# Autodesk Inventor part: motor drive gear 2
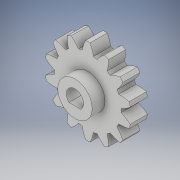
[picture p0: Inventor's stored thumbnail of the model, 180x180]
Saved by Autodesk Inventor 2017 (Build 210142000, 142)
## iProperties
Created: 2016-07
Part Number: motor drive gear 2
Material: Generic
Document SubType Name: Modeling
Designer: Stan
Density: 1 g/cm^3
Appearance: Default
Author: Stan
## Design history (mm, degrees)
sketch "Sketch1"
  geometry: L1 (-2.203, -2.286)-(2.203, -2.286); A1 r 13.958 centre (-11.606, 9.5) between (2.097, 12.157) and (0.818, 15.862); A2 r 13.958 centre (-11.606, 9.5) between (2.097, 12.157) and (0.818, 15.862); A3 r 13.958 centre (-11.606, 9.5) between (2.097, 12.157) and (0.818, 15.862); A4 r 13.958 centre (11.606, 9.5) between (-0.818, 15.862) and (-2.097, 12.157); A5 r 13.958 centre (11.606, 9.5) between (-0.822, 15.854) and (-2.097, 12.157); A6 r 13.958 centre (-11.606, 9.5) between (2.097, 12.157) and (0.822, 15.854); A7 r 13.958 centre (-14.578, 3.524) between (-3.386, 11.863) and (-6.145, 14.646); A8 r 13.958 centre (-14.578, 3.524) between (-3.386, 11.863) and (-6.145, 14.646); A9 r 13.958 centre (-14.578, 3.524) between (-3.386, 11.863) and (-6.145, 14.646); A10 r 13.958 centre (6.334, 13.595) between (-7.619, 13.936) and (-7.164, 10.044); A11 r 13.958 centre (6.334, 13.595) between (-7.62, 13.927) and (-7.164, 10.044); A12 r 13.958 centre (-14.578, 3.524) between (-3.386, 11.863) and (-6.138, 14.64); A13 r 13.958 centre (-14.663, -3.15) between (-8.198, 9.22) and (-11.891, 10.529); A14 r 13.958 centre (-14.663, -3.15) between (-8.198, 9.22) and (-11.891, 10.529); A15 r 13.958 centre (-14.663, -3.15) between (-8.198, 9.22) and (-11.891, 10.529); A16 r 13.958 centre (-0.191, 14.997) between (-12.911, 9.25) and (-10.812, 5.94); A17 r 13.958 centre (-0.191, 14.997) between (-12.908, 9.242) and (-10.812, 5.94); A18 r 13.958 centre (-14.663, -3.15) between (-8.198, 9.22) and (-11.882, 10.528); A19 r 13.958 centre (-11.844, -9.201) between (-11.386, 4.75) and (-15.282, 4.327); A20 r 13.958 centre (-11.844, -9.201) between (-11.386, 4.75) and (-15.282, 4.327); A21 r 13.958 centre (-11.844, -9.201) between (-11.386, 4.75) and (-15.282, 4.327); A22 r 13.958 centre (-6.679, 13.428) between (-15.646, 2.732) and (-12.319, 0.661); A23 r 13.958 centre (-6.679, 13.428) between (-15.639, 2.726) and (-12.319, 0.661); A24 r 13.958 centre (-11.844, -9.201) between (-11.386, 4.75) and (-15.273, 4.329); A25 r 13.958 centre (-6.679, -13.428) between (-12.319, -0.661) and (-15.646, -2.732); A26 r 13.958 centre (-6.679, -13.428) between (-12.319, -0.661) and (-15.646, -2.732); A27 r 13.958 centre (-6.679, -13.428) between (-12.319, -0.661) and (-15.646, -2.732); A28 r 13.958 centre (-11.844, 9.201) between (-15.282, -4.327) and (-11.386, -4.75); A29 r 13.958 centre (-11.844, 9.201) between (-15.273, -4.329) and (-11.386, -4.75); A30 r 13.958 centre (-6.679, -13.428) between (-12.319, -0.661) and (-15.639, -2.726); A31 r 13.958 centre (-0.191, -14.997) between (-10.812, -5.94) and (-12.911, -9.25); A32 r 13.958 centre (-0.191, -14.997) between (-10.812, -5.94) and (-12.911, -9.25); A33 r 13.958 centre (-0.191, -14.997) between (-10.812, -5.94) and (-12.911, -9.25); A34 r 13.958 centre (-14.663, 3.15) between (-11.891, -10.529) and (-8.198, -9.22); A35 r 13.958 centre (-14.663, 3.15) between (-11.882, -10.528) and (-8.198, -9.22); A36 r 13.958 centre (-0.191, -14.997) between (-10.812, -5.94) and (-12.908, -9.242); A37 r 13.958 centre (6.334, -13.595) between (-7.164, -10.044) and (-7.619, -13.936); A38 r 13.958 centre (6.334, -13.595) between (-7.164, -10.044) and (-7.619, -13.936); A39 r 13.958 centre (6.334, -13.595) between (-7.164, -10.044) and (-7.619, -13.936); A40 r 13.958 centre (-14.578, -3.524) between (-6.145, -14.646) and (-3.386, -11.863); A41 r 13.958 centre (-14.578, -3.524) between (-6.138, -14.64) and (-3.386, -11.863); A42 r 13.958 centre (6.334, -13.595) between (-7.164, -10.044) and (-7.62, -13.927); A43 r 13.958 centre (11.606, -9.5) between (-2.097, -12.157) and (-0.818, -15.862); A44 r 13.958 centre (11.606, -9.5) between (-2.097, -12.157) and (-0.818, -15.862); A45 r 13.958 centre (11.606, -9.5) between (-2.097, -12.157) and (-0.818, -15.862); A46 r 13.958 centre (-11.606, -9.5) between (0.818, -15.862) and (2.097, -12.157); A47 r 13.958 centre (-11.606, -9.5) between (0.822, -15.854) and (2.097, -12.157); A48 r 13.958 centre (11.606, -9.5) between (-2.097, -12.157) and (-0.822, -15.854); A49 r 13.958 centre (14.578, -3.524) between (3.386, -11.863) and (6.145, -14.646); A50 r 13.958 centre (14.578, -3.524) between (3.386, -11.863) and (6.145, -14.646); A51 r 13.958 centre (14.578, -3.524) between (3.386, -11.863) and (6.145, -14.646); A52 r 13.958 centre (-6.334, -13.595) between (7.619, -13.936) and (7.164, -10.044); A53 r 13.958 centre (-6.334, -13.595) between (7.62, -13.927) and (7.164, -10.044); A54 r 13.958 centre (14.578, -3.524) between (3.386, -11.863) and (6.138, -14.64); A55 r 13.958 centre (14.663, 3.15) between (8.198, -9.22) and (11.891, -10.529); A56 r 13.958 centre (14.663, 3.15) between (8.198, -9.22) and (11.891, -10.529); A57 r 13.958 centre (14.663, 3.15) between (8.198, -9.22) and (11.891, -10.529); A58 r 13.958 centre (14.663, 3.15) between (8.198, -9.22) and (11.882, -10.528); A59 r 13.958 centre (0.191, -14.997) between (12.911, -9.25) and (10.812, -5.94); A60 r 13.958 centre (0.191, -14.997) between (12.908, -9.242) and (10.812, -5.94); A61 r 13.958 centre (11.844, 9.201) between (11.386, -4.75) and (15.282, -4.327); A62 r 13.958 centre (11.844, 9.201) between (11.386, -4.75) and (15.282, -4.327); A63 r 13.958 centre (11.844, 9.201) between (11.386, -4.75) and (15.282, -4.327); A64 r 13.958 centre (6.679, -13.428) between (15.646, -2.732) and (12.319, -0.661)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
  constraints: 288 point on circle, 115 centre point, 2 end point, 1 coincident
  dimensions: "d2" = 6.35 diameter of A115; "d4" = 5.461 dimension on A115 L1
extrude "Extrusion2" new body sketch "Sketch1" distance "d5" = 6.35; taper "d6" = 0 deg
sketch "Sketch2"
  geometry: C1 r 6.35 at (0, 0); 1 further point
  constraints: 1 centre point, 1 coincident
  dimensions: "d7" = 12.7 diameter of C1
extrude "Extrusion3" join sketch "Sketch2" distance "d8" = 4.7625; taper "d9" = 0 deg
sketch "Sketch3"
  geometry: L1 (-2.203, -2.286)-(2.203, -2.286) reference; L2 (-2.203, -2.286)-(2.203, -2.286); A1 r 3.175 centre (0, 0) between (2.203, -2.286) and (-2.203, -2.286); 1 further point
  constraints: 2 end point, 2 point on circle, 1 centre point, 1 coincident, 1 collinear
extrude "Extrusion4" cut sketch "Sketch3" distance "d10" = 4.7625; taper "d11" = 0 deg
body "Solid2"
